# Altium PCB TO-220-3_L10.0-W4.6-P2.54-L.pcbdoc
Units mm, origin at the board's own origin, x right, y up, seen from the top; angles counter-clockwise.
Board outline 22.9 x 18.3 mm, 2 copper layers (Top Layer, Bottom Layer), stack 0 mm thick; 1 components, 0 nets, 3 pads, 0 vias.
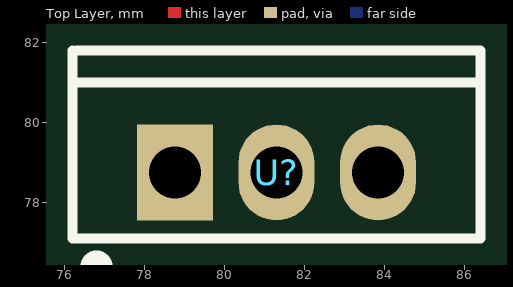
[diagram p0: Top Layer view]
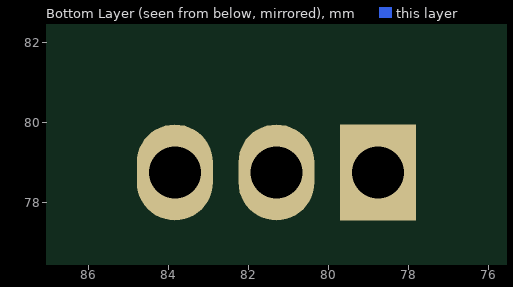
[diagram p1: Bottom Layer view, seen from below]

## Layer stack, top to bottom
Top Layer: signal copper (thickness not stored)
Bottom Layer: signal copper (thickness not stored)

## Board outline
92.75,69.85 69.85,69.85 69.85,88.15 92.75,88.15

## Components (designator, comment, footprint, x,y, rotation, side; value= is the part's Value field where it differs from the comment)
U? "" TO-220-3_L10.0-W4.6-P2.54-L 81.3,78.75 r0 top

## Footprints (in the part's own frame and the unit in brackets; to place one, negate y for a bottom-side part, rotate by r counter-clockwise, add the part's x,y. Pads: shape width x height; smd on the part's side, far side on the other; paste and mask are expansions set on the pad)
TO-220-3_L10.0-W4.6-P2.54-L [mm]
  rect 1.9x2.4 hole 1.3 paste+0 mask+0.05: 1(-2.54,0)
  oval 1.9x2.4 hole 1.3 paste+0 mask+0.05: 2(0,0) 3(2.54,0)
  silkscreen extent -5.1,-2.55 5.1,3.05

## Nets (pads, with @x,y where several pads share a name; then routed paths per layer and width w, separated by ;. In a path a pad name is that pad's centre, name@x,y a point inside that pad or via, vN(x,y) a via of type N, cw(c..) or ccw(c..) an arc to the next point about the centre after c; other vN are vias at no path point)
pads on no net: U?.1 U?.2 U?.3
